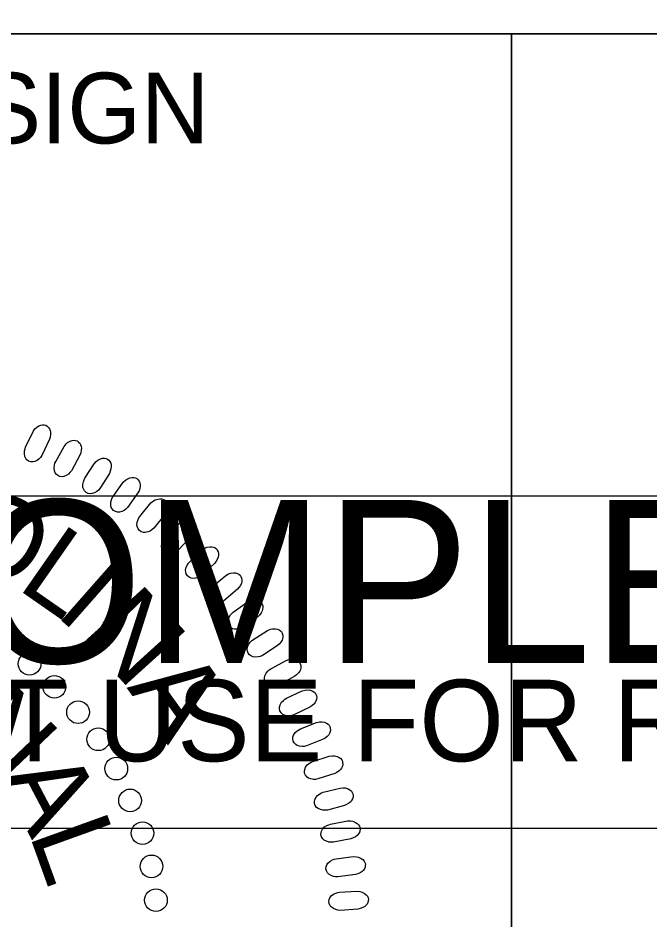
# Model space of a CAD drawing. Extents: x 505602 to 507286, y 483109 to 484209.
# Drawn here: x 507134.2 to 507178.9, y 484096 to 484159.8 of the extents above; entities that cross this region are included whole.
import ezdxf

# ---------------------------------------------------------------- set-up
doc = ezdxf.new("R2010")
doc.units = 0
for name, color, linetype in [('Sheet PE Seal Cell', 7, 'Continuous'), ('Sheet Profile CELL', 7, 'Continuous'), ('Sheet Sticker Incomplete CELL', 7, 'Continuous')]:
    doc.layers.add(name, color=color, linetype=linetype)

msp = doc.modelspace()

# ---------------------------------------------------------------- linework, layer by layer
at = {"layer": 'Sheet PE Seal Cell'}
for points in [[(507134.756, 484129.454), (507135.278, 484130.563), (507135.405, 484130.746), (507135.512, 484130.85), (507135.686, 484130.956), (507135.821, 484131.014), (507135.956, 484131.038), (507136.068, 484131.029), (507136.178, 484130.999), (507136.27, 484130.933), (507136.366, 484130.856), (507136.435, 484130.757), (507136.487, 484130.622), (507136.508, 484130.525), (507136.505, 484130.36), (507136.482, 484130.173), (507136.435, 484130.018), (507135.906, 484128.878), (507135.814, 484128.735), (507135.713, 484128.627), (507135.564, 484128.521), (507135.403, 484128.443), (507135.281, 484128.412), (507135.114, 484128.425), (507134.97, 484128.471), (507134.852, 484128.57), (507134.779, 484128.66), (507134.706, 484128.804), (507134.67, 484129.008), (507134.686, 484129.2), (507134.714, 484129.329)], [(507136.88, 484128.438), (507137.471, 484129.513), (507137.609, 484129.687), (507137.722, 484129.784), (507137.902, 484129.879), (507138.04, 484129.928), (507138.177, 484129.944), (507138.288, 484129.929), (507138.396, 484129.892), (507138.485, 484129.82), (507138.575, 484129.736), (507138.638, 484129.634), (507138.682, 484129.496), (507138.695, 484129.397), (507138.683, 484129.234), (507138.648, 484129.047), (507138.591, 484128.897), (507137.992, 484127.792), (507137.89, 484127.655), (507137.784, 484127.554), (507137.629, 484127.457), (507137.462, 484127.389), (507137.339, 484127.366), (507137.173, 484127.389), (507137.032, 484127.444), (507136.92, 484127.55), (507136.852, 484127.645), (507136.789, 484127.794), (507136.766, 484128), (507136.794, 484128.189), (507136.83, 484128.318)], [(507138.938, 484127.253), (507139.595, 484128.289), (507139.744, 484128.454), (507139.863, 484128.544), (507140.049, 484128.627), (507140.19, 484128.668), (507140.327, 484128.675), (507140.437, 484128.652), (507140.543, 484128.609), (507140.626, 484128.532), (507140.711, 484128.442), (507140.768, 484128.336), (507140.802, 484128.196), (507140.81, 484128.096), (507140.787, 484127.933), (507140.741, 484127.75), (507140.674, 484127.604), (507140.007, 484126.539), (507139.897, 484126.408), (507139.784, 484126.314), (507139.623, 484126.227), (507139.454, 484126.169), (507139.329, 484126.154), (507139.164, 484126.188), (507139.027, 484126.251), (507138.923, 484126.365), (507138.861, 484126.464), (507138.807, 484126.616), (507138.797, 484126.822), (507138.837, 484127.01), (507138.881, 484127.136)], [(507140.938, 484125.98), (507141.659, 484126.972), (507141.818, 484127.128), (507141.943, 484127.21), (507142.133, 484127.281), (507142.276, 484127.313), (507142.413, 484127.312), (507142.522, 484127.282), (507142.625, 484127.232), (507142.703, 484127.151), (507142.782, 484127.056), (507142.832, 484126.946), (507142.858, 484126.804), (507142.86, 484126.704), (507142.826, 484126.543), (507142.769, 484126.363), (507142.693, 484126.221), (507141.96, 484125.2), (507141.842, 484125.076), (507141.723, 484124.99), (507141.558, 484124.913), (507141.384, 484124.866), (507141.259, 484124.859), (507141.097, 484124.903), (507140.964, 484124.975), (507140.866, 484125.095), (507140.811, 484125.197), (507140.767, 484125.352), (507140.77, 484125.559), (507140.821, 484125.744), (507140.873, 484125.867)], [(507142.832, 484124.564), (507143.614, 484125.509), (507143.783, 484125.654), (507143.912, 484125.728), (507144.107, 484125.788), (507144.251, 484125.81), (507144.389, 484125.8), (507144.495, 484125.764), (507144.594, 484125.707), (507144.668, 484125.621), (507144.741, 484125.521), (507144.783, 484125.409), (507144.8, 484125.265), (507144.796, 484125.166), (507144.751, 484125.008), (507144.683, 484124.831), (507144.599, 484124.694), (507143.804, 484123.721), (507143.678, 484123.604), (507143.554, 484123.526), (507143.384, 484123.46), (507143.208, 484123.424), (507143.082, 484123.424), (507142.923, 484123.478), (507142.795, 484123.559), (507142.705, 484123.685), (507142.657, 484123.79), (507142.623, 484123.947), (507142.639, 484124.154), (507142.701, 484124.336), (507142.761, 484124.454)], [(507144.603, 484123.05), (507145.444, 484123.944), (507145.621, 484124.078), (507145.755, 484124.144), (507145.953, 484124.191), (507146.099, 484124.204), (507146.235, 484124.186), (507146.339, 484124.143), (507146.434, 484124.081), (507146.502, 484123.99), (507146.569, 484123.886), (507146.604, 484123.771), (507146.612, 484123.626), (507146.601, 484123.527), (507146.547, 484123.372), (507146.468, 484123.2), (507146.376, 484123.069), (507145.52, 484122.148), (507145.388, 484122.04), (507145.259, 484121.969), (507145.085, 484121.914), (507144.908, 484121.889), (507144.782, 484121.897), (507144.626, 484121.961), (507144.504, 484122.049), (507144.423, 484122.18), (507144.381, 484122.288), (507144.356, 484122.448), (507144.385, 484122.654), (507144.459, 484122.83), (507144.526, 484122.945)], [(507146.348, 484121.356), (507147.243, 484122.196), (507147.428, 484122.318), (507147.566, 484122.376), (507147.766, 484122.411), (507147.912, 484122.415), (507148.047, 484122.388), (507148.148, 484122.339), (507148.24, 484122.271), (507148.302, 484122.175), (507148.362, 484122.067), (507148.39, 484121.95), (507148.389, 484121.806), (507148.371, 484121.707), (507148.308, 484121.556), (507148.219, 484121.39), (507148.117, 484121.264), (507147.206, 484120.399), (507147.067, 484120.299), (507146.935, 484120.236), (507146.757, 484120.192), (507146.578, 484120.179), (507146.453, 484120.195), (507146.302, 484120.268), (507146.185, 484120.364), (507146.112, 484120.5), (507146.077, 484120.61), (507146.063, 484120.771), (507146.105, 484120.974), (507146.19, 484121.147), (507146.264, 484121.257)], [(507147.96, 484119.61), (507148.905, 484120.392), (507149.099, 484120.503), (507149.24, 484120.552), (507149.441, 484120.573), (507149.588, 484120.568), (507149.721, 484120.532), (507149.818, 484120.477), (507149.906, 484120.404), (507149.961, 484120.304), (507150.014, 484120.193), (507150.035, 484120.074), (507150.025, 484119.93), (507150.001, 484119.833), (507149.929, 484119.686), (507149.829, 484119.526), (507149.72, 484119.407), (507148.756, 484118.6), (507148.611, 484118.509), (507148.475, 484118.455), (507148.295, 484118.423), (507148.116, 484118.42), (507147.992, 484118.444), (507147.846, 484118.526), (507147.736, 484118.63), (507147.671, 484118.77), (507147.643, 484118.882), (507147.639, 484119.044), (507147.693, 484119.244), (507147.789, 484119.41), (507147.87, 484119.516)], [(507149.42, 484117.788), (507150.413, 484118.508), (507150.612, 484118.607), (507150.756, 484118.647), (507150.96, 484118.656), (507151.105, 484118.641), (507151.235, 484118.598), (507151.329, 484118.536), (507151.412, 484118.457), (507151.461, 484118.354), (507151.507, 484118.241), (507151.52, 484118.121), (507151.501, 484117.978), (507151.472, 484117.882), (507151.39, 484117.739), (507151.28, 484117.586), (507151.164, 484117.474), (507150.152, 484116.73), (507150.001, 484116.649), (507149.861, 484116.602), (507149.68, 484116.581), (507149.501, 484116.59), (507149.379, 484116.622), (507149.239, 484116.714), (507149.135, 484116.823), (507149.079, 484116.967), (507149.058, 484117.081), (507149.064, 484117.243), (507149.131, 484117.439), (507149.237, 484117.599), (507149.324, 484117.7)], [(507150.821, 484115.841), (507151.857, 484116.499), (507152.062, 484116.585), (507152.208, 484116.616), (507152.411, 484116.612), (507152.556, 484116.588), (507152.683, 484116.536), (507152.773, 484116.469), (507152.85, 484116.385), (507152.893, 484116.28), (507152.932, 484116.163), (507152.938, 484116.043), (507152.909, 484115.9), (507152.874, 484115.807), (507152.783, 484115.67), (507152.664, 484115.524), (507152.542, 484115.419), (507151.485, 484114.74), (507151.329, 484114.668), (507151.187, 484114.632), (507151.004, 484114.622), (507150.826, 484114.642), (507150.707, 484114.681), (507150.572, 484114.781), (507150.476, 484114.897), (507150.429, 484115.044), (507150.415, 484115.159), (507150.431, 484115.321), (507150.51, 484115.512), (507150.626, 484115.665), (507150.72, 484115.76)], [(507152.082, 484113.792), (507153.157, 484114.382), (507153.367, 484114.455), (507153.515, 484114.477), (507153.717, 484114.461), (507153.86, 484114.428), (507153.984, 484114.368), (507154.07, 484114.295), (507154.141, 484114.207), (507154.178, 484114.099), (507154.209, 484113.98), (507154.207, 484113.859), (507154.17, 484113.719), (507154.129, 484113.629), (507154.03, 484113.497), (507153.901, 484113.359), (507153.773, 484113.262), (507152.675, 484112.651), (507152.515, 484112.589), (507152.371, 484112.561), (507152.188, 484112.563), (507152.012, 484112.594), (507151.895, 484112.64), (507151.767, 484112.749), (507151.678, 484112.871), (507151.641, 484113.02), (507151.634, 484113.136), (507151.66, 484113.296), (507151.751, 484113.482), (507151.876, 484113.628), (507151.976, 484113.717)], [(507153.189, 484111.709), (507154.299, 484112.231), (507154.514, 484112.29), (507154.662, 484112.303), (507154.864, 484112.273), (507155.004, 484112.231), (507155.124, 484112.164), (507155.205, 484112.087), (507155.271, 484111.993), (507155.3, 484111.883), (507155.324, 484111.762), (507155.315, 484111.642), (507155.269, 484111.505), (507155.222, 484111.417), (507155.115, 484111.292), (507154.978, 484111.162), (507154.843, 484111.074), (507153.709, 484110.532), (507153.546, 484110.481), (507153.4, 484110.462), (507153.219, 484110.475), (507153.044, 484110.517), (507152.93, 484110.571), (507152.809, 484110.688), (507152.728, 484110.815), (507152.7, 484110.967), (507152.701, 484111.083), (507152.737, 484111.241), (507152.84, 484111.421), (507152.974, 484111.558), (507153.079, 484111.64)], [(507154.169, 484109.548), (507155.31, 484109.999), (507155.527, 484110.044), (507155.676, 484110.048), (507155.875, 484110.006), (507156.013, 484109.955), (507156.128, 484109.881), (507156.204, 484109.798), (507156.264, 484109.701), (507156.286, 484109.589), (507156.302, 484109.467), (507156.286, 484109.348), (507156.231, 484109.214), (507156.179, 484109.129), (507156.065, 484109.011), (507155.92, 484108.889), (507155.78, 484108.81), (507154.614, 484108.341), (507154.448, 484108.299), (507154.301, 484108.29), (507154.12, 484108.315), (507153.949, 484108.367), (507153.839, 484108.429), (507153.725, 484108.553), (507153.652, 484108.684), (507153.634, 484108.838), (507153.642, 484108.954), (507153.688, 484109.109), (507153.802, 484109.282), (507153.944, 484109.411), (507154.054, 484109.486)], [(507155.042, 484107.233), (507156.21, 484107.612), (507156.43, 484107.644), (507156.579, 484107.638), (507156.775, 484107.583), (507156.909, 484107.525), (507157.02, 484107.443), (507157.09, 484107.356), (507157.143, 484107.255), (507157.159, 484107.142), (507157.168, 484107.019), (507157.143, 484106.902), (507157.08, 484106.771), (507157.023, 484106.689), (507156.901, 484106.579), (507156.749, 484106.467), (507156.604, 484106.396), (507155.411, 484106.001), (507155.243, 484105.97), (507155.097, 484105.97), (507154.918, 484106.006), (507154.75, 484106.069), (507154.644, 484106.137), (507154.538, 484106.268), (507154.473, 484106.404), (507154.465, 484106.559), (507154.48, 484106.673), (507154.536, 484106.825), (507154.66, 484106.991), (507154.81, 484107.111), (507154.924, 484107.179)], [(507155.788, 484105.06), (507156.976, 484105.364), (507157.197, 484105.383), (507157.346, 484105.368), (507157.538, 484105.301), (507157.669, 484105.234), (507157.773, 484105.145), (507157.838, 484105.054), (507157.885, 484104.95), (507157.894, 484104.836), (507157.894, 484104.713), (507157.863, 484104.598), (507157.792, 484104.471), (507157.73, 484104.393), (507157.601, 484104.291), (507157.442, 484104.188), (507157.293, 484104.127), (507156.078, 484103.808), (507155.908, 484103.787), (507155.762, 484103.796), (507155.585, 484103.843), (507155.422, 484103.917), (507155.32, 484103.991), (507155.224, 484104.128), (507155.167, 484104.268), (507155.169, 484104.423), (507155.191, 484104.537), (507155.256, 484104.685), (507155.39, 484104.842), (507155.548, 484104.952), (507155.666, 484105.013)], [(507156.297, 484102.806), (507157.502, 484103.035), (507157.725, 484103.039), (507157.872, 484103.015), (507158.059, 484102.936), (507158.185, 484102.861), (507158.285, 484102.766), (507158.343, 484102.671), (507158.384, 484102.564), (507158.385, 484102.451), (507158.378, 484102.327), (507158.339, 484102.214), (507158.261, 484102.092), (507158.194, 484102.018), (507158.059, 484101.924), (507157.894, 484101.832), (507157.742, 484101.78), (507156.508, 484101.537), (507156.337, 484101.528), (507156.192, 484101.546), (507156.019, 484101.604), (507155.861, 484101.688), (507155.764, 484101.768), (507155.675, 484101.912), (507155.628, 484102.055), (507155.639, 484102.209), (507155.669, 484102.321), (507155.743, 484102.465), (507155.887, 484102.613), (507156.052, 484102.714), (507156.173, 484102.767)], [(507156.695, 484100.367), (507157.913, 484100.52), (507158.135, 484100.51), (507158.28, 484100.476), (507158.462, 484100.386), (507158.584, 484100.304), (507158.677, 484100.202), (507158.729, 484100.104), (507158.763, 484099.995), (507158.757, 484099.881), (507158.742, 484099.758), (507158.696, 484099.647), (507158.61, 484099.531), (507158.539, 484099.462), (507158.398, 484099.376), (507158.228, 484099.294), (507158.072, 484099.252), (507156.826, 484099.087), (507156.655, 484099.089), (507156.511, 484099.116), (507156.342, 484099.185), (507156.189, 484099.279), (507156.098, 484099.365), (507156.018, 484099.513), (507155.981, 484099.66), (507156.002, 484099.812), (507156.038, 484099.922), (507156.121, 484100.061), (507156.274, 484100.201), (507156.444, 484100.29), (507156.569, 484100.335)], [(507156.939, 484098.002), (507158.163, 484098.078), (507158.384, 484098.054), (507158.527, 484098.012), (507158.704, 484097.91), (507158.819, 484097.82), (507158.905, 484097.713), (507158.951, 484097.611), (507158.979, 484097.5), (507158.966, 484097.387), (507158.944, 484097.266), (507158.89, 484097.158), (507158.797, 484097.047), (507158.721, 484096.983), (507158.576, 484096.906), (507158.401, 484096.835), (507158.243, 484096.803), (507156.989, 484096.717), (507156.819, 484096.729), (507156.676, 484096.765), (507156.512, 484096.844), (507156.366, 484096.948), (507156.28, 484097.039), (507156.21, 484097.192), (507156.181, 484097.341), (507156.211, 484097.492), (507156.255, 484097.6), (507156.346, 484097.733), (507156.508, 484097.862), (507156.683, 484097.941), (507156.81, 484097.979)]]:
    msp.add_lwpolyline(points, close=True, dxfattribs=at)
for centre in [(507135.036, 484114.147), (507136.787, 484112.513), (507138.459, 484110.72), (507139.891, 484108.807), (507141.165, 484106.735), (507142.137, 484104.486), (507143.012, 484102.175), (507143.648, 484099.825), (507143.966, 484097.434)]:
    msp.add_circle(centre, 0.801, dxfattribs=at)
at = {"layer": 'Sheet Profile CELL'}
msp.add_line((507169.08, 484158.662), (507169.08, 484046.212), dxfattribs=at)
for points in [[(507069.03, 484183.712), (507269.08, 484183.712), (507269.08, 484158.662), (507069.03, 484158.662)], [(507069.03, 484158.662), (507169.08, 484158.662), (507169.08, 484046.162), (507069.03, 484046.162)], [(507169.08, 484158.662), (507269.08, 484158.662), (507269.08, 484046.162), (507169.08, 484046.162)]]:
    msp.add_lwpolyline(points, close=True, dxfattribs=at)
at = {"layer": 'Sheet Sticker Incomplete CELL'}
msp.add_lwpolyline([(507095.597, 484102.505), (507095.597, 484126.005), (507242.597, 484126.005), (507242.597, 484102.505)], close=True, dxfattribs=at)

# ---------------------------------------------------------------- texts
at = {"layer": 'Sheet PE Seal Cell'}
for s, rotation, p in [('O', 331.63025, (507129.326, 484122.044)), ('L', 325.14089, (507134.059, 484119.513)), ('I', 318.65154, (507136.752, 484117.66)), ('N', 312.16218, (507138.557, 484116.24)), ('A', 305.67282, (507141.877, 484112.46)), ('N', 313.65025, (507129.525, 484109.202)), ('A', 297.77065, (507132.862, 484106.121)), ('L', 289.83086, (507134.985, 484102.126))]:
    msp.add_text(s, height=5.669, rotation=rotation, dxfattribs=at).set_placement(p)
at = {"layer": 'Sheet Profile CELL'}
msp.add_text('ROADWAY DESIGN', height=5.0001, dxfattribs=at).set_placement((507085.692, 484150.924))
at = {"layer": 'Sheet Sticker Incomplete CELL'}
for s, height, p in [('INCOMPLETE PLANS', 11.52, (507104.547, 484114.205)), ('DO NOT USE FOR R/W ACQUISITION', 5.76, (507107.797, 484107.255))]:
    msp.add_text(s, height=height, dxfattribs=at).set_placement(p)

doc.saveas('drawing.dxf')
